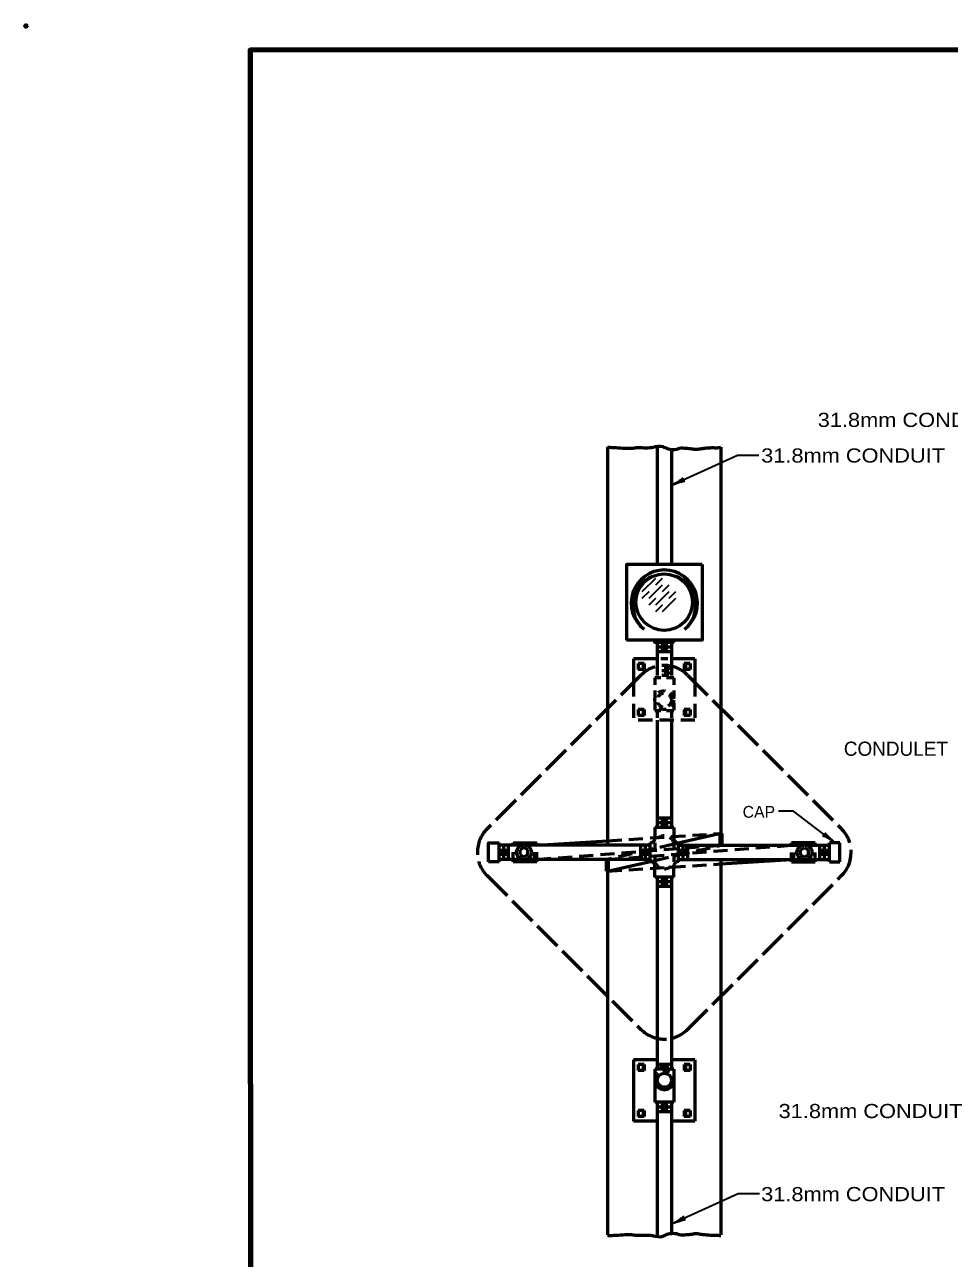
# Model space of a CAD drawing. Extents: x -31 to 825, y 0 to 544.
# Drawn here: x -31 to 204.1, y 230.5 to 544.3 of the extents above; entities that cross this region are included whole.
import ezdxf

# ---------------------------------------------------------------- set-up
doc = ezdxf.new("R2010")
doc.units = 0
doc.header["$LTSCALE"] = 1.2
doc.header["$PDMODE"] = 32
doc.header["$PDSIZE"] = 0.6
for name, pattern in [('LONG_DASHED', [7.5, 6, -1.5]), ('MEDIUM_DASHED', [4.5, 3, -1.5]), ('SHORT_DASHED', [2.7, 1.5, -1.2])]:
    doc.linetypes.add(name, pattern=pattern)
doc.layers.add('1', color=7, linetype='Continuous', lineweight=53)

msp = doc.modelspace()

# ---------------------------------------------------------------- linework, layer by layer
at = {"layer": '1'}
for p, q in [((117.259, 436.827), (117.259, 335.556)), ((129.859, 436.956), (129.859, 406.956)), ((133.459, 436.418), (133.459, 406.956)), ((146.059, 436.827), (146.059, 338.556)), ((129.859, 387.756), (129.859, 380.556)), ((132.559, 386.556), (130.759, 386.556)), ((133.459, 387.756), (133.459, 380.556)), ((134.059, 387.156), (134.059, 387.756)), ((129.859, 382.956), (123.859, 382.956)), ((123.859, 382.956), (123.859, 376.956)), ((133.459, 385.956), (129.859, 385.956)), ((133.459, 384.756), (129.859, 384.756)), ((132.559, 385.356), (130.759, 385.356)), ((132.559, 382.956), (130.759, 382.956)), ((139.459, 382.956), (133.459, 382.956)), ((139.459, 382.956), (139.459, 376.956)), ((125.059, 381.756), (125.059, 380.256)), ((126.559, 381.756), (125.059, 381.756)), ((126.559, 380.256), (125.059, 380.256)), ((126.259, 381.756), (126.259, 380.256)), ((126.559, 381.756), (126.559, 380.256)), ((136.759, 381.756), (136.759, 380.256)), ((138.259, 381.756), (136.759, 381.756)), ((138.259, 380.256), (136.759, 380.256)), ((137.059, 381.756), (137.059, 380.256)), ((138.259, 381.756), (138.259, 380.256)), ((129.859, 367.356), (129.859, 340.056)), ((133.459, 367.356), (133.459, 340.056)), ((133.459, 342.456), (129.859, 342.456)), ((134.059, 340.056), (129.259, 340.056)), ((129.259, 340.056), (129.259, 337.056)), ((133.459, 341.256), (129.859, 341.256)), ((132.559, 341.856), (130.759, 341.856)), ((132.559, 340.656), (130.759, 340.656)), ((134.059, 340.056), (134.059, 337.056)), ((89.659, 331.356), (89.659, 336.156)), ((93.259, 336.156), (99.259, 336.156)), ((93.259, 335.556), (93.259, 336.156)), ((99.259, 335.556), (117.259, 336.71)), ((128.059, 331.356), (128.059, 336.156)), ((146.059, 338.556), (134.059, 335.806)), ((135.259, 331.356), (135.259, 336.156)), ((170.037, 336.139), (164.037, 336.139)), ((164.037, 335.556), (164.037, 336.139)), ((170.037, 335.539), (170.037, 336.139)), ((173.638, 331.339), (173.638, 336.139)), ((176.338, 336.139), (173.638, 336.139)), ((176.338, 331.339), (176.338, 336.139)), ((95.336, 335.556), (89.659, 335.556)), ((90.259, 332.856), (90.259, 334.656)), ((90.859, 331.956), (90.859, 335.556)), ((91.459, 332.856), (91.459, 334.656)), ((92.059, 331.956), (92.059, 335.556)), ((95.982, 334.956), (94.98, 334.356)), ((94.98, 333.156), (94.98, 334.356)), ((94.98, 333.156), (95.982, 332.556)), ((96.984, 334.356), (95.982, 334.956)), ((96.984, 333.156), (95.982, 332.556)), ((96.984, 333.156), (96.984, 334.356)), ((125.659, 331.956), (125.659, 335.556)), ((126.259, 332.856), (126.259, 334.656)), ((126.859, 331.956), (126.859, 335.556)), ((127.459, 332.856), (127.459, 334.656)), ((135.859, 332.856), (135.859, 334.656)), ((136.459, 331.956), (136.459, 335.556)), ((137.059, 332.856), (137.059, 334.656)), ((137.659, 331.956), (137.659, 335.556)), ((166.312, 334.339), (167.314, 334.939)), ((166.312, 333.139), (166.312, 334.339)), ((166.312, 333.139), (167.314, 332.539)), ((167.314, 334.939), (168.316, 334.339)), ((168.316, 333.139), (167.314, 332.539)), ((167.911, 335.556), (173.659, 335.556)), ((168.316, 333.139), (168.316, 334.339)), ((171.238, 331.939), (171.238, 335.539)), ((171.838, 332.839), (171.838, 334.639)), ((172.438, 331.939), (172.438, 335.539)), ((173.037, 332.839), (173.037, 334.639)), ((89.659, 331.356), (86.959, 331.356)), ((95.383, 331.956), (89.659, 331.956)), ((93.259, 331.356), (93.259, 331.956)), ((99.259, 331.356), (93.259, 331.356)), ((99.259, 331.356), (99.259, 331.956)), ((117.259, 328.956), (129.259, 331.706)), ((129.259, 327.456), (129.259, 330.456)), ((134.059, 327.456), (134.059, 330.456)), ((146.059, 331.956), (146.059, 236.427)), ((146.059, 330.803), (164.037, 331.956)), ((164.037, 331.339), (164.037, 331.956)), ((164.037, 331.339), (170.037, 331.339)), ((167.963, 331.956), (173.659, 331.956)), ((170.037, 331.339), (170.037, 331.939)), ((173.638, 331.339), (176.338, 331.339)), ((117.259, 328.956), (117.259, 236.427)), ((134.059, 327.456), (129.259, 327.456)), ((129.859, 327.456), (129.859, 278.558)), ((132.559, 326.856), (130.759, 326.856)), ((133.459, 327.456), (133.459, 278.558)), ((133.459, 326.256), (129.859, 326.256)), ((133.459, 325.056), (129.859, 325.056)), ((132.559, 325.656), (130.759, 325.656)), ((123.859, 280.956), (123.859, 265.356)), ((129.859, 280.956), (123.859, 280.956)), ((125.059, 279.756), (125.059, 278.256)), ((126.559, 279.756), (125.059, 279.756)), ((126.259, 279.756), (126.259, 278.256)), ((126.559, 279.756), (126.559, 278.256)), ((133.459, 279.756), (129.859, 279.756)), ((139.459, 280.956), (133.459, 280.956)), ((136.759, 279.756), (136.759, 278.256)), ((138.259, 279.756), (136.759, 279.756)), ((137.059, 279.756), (137.059, 278.256)), ((138.259, 279.756), (138.259, 278.256)), ((139.459, 280.956), (139.459, 265.356)), ((126.559, 278.256), (125.059, 278.256)), ((134.059, 278.558), (129.259, 278.558)), ((129.259, 278.558), (129.259, 278.211)), ((129.259, 278.211), (129.259, 273.402)), ((132.859, 279.156), (130.459, 279.156)), ((134.059, 278.558), (134.059, 275.462)), ((138.259, 278.256), (136.759, 278.256)), ((129.259, 273.402), (129.259, 270.158)), ((134.059, 275.462), (134.059, 270.158)), ((134.059, 270.158), (129.259, 270.158)), ((129.859, 270.158), (129.859, 236.427)), ((133.459, 270.158), (133.459, 236.427)), ((125.059, 268.056), (125.059, 266.556)), ((126.559, 268.056), (125.059, 268.056)), ((126.259, 268.056), (126.259, 266.556)), ((126.559, 268.056), (126.559, 266.556)), ((133.459, 268.958), (129.859, 268.958)), ((133.459, 267.758), (129.859, 267.758)), ((129.859, 267.756), (129.859, 265.356)), ((132.559, 269.558), (130.759, 269.558)), ((132.559, 268.358), (130.759, 268.358)), ((133.459, 267.756), (133.459, 265.356)), ((136.759, 268.056), (136.759, 266.556)), ((138.259, 268.056), (136.759, 268.056)), ((137.059, 268.056), (137.059, 266.556)), ((138.259, 268.056), (138.259, 266.556)), ((129.859, 265.356), (123.859, 265.356)), ((126.559, 266.556), (125.059, 266.556)), ((139.459, 265.356), (133.459, 265.356)), ((138.259, 266.556), (136.759, 266.556))]:
    msp.add_line(p, q, dxfattribs=at)
at = {"layer": '1', "lineweight": 25}
for p, q in [((124.381, 400.118), (126.078, 401.815)), ((124.381, 400.118), (126.078, 401.815)), ((126.078, 398.421), (127.775, 400.118)), ((127.775, 396.724), (129.472, 398.421)), ((129.472, 395.027), (131.169, 396.724))]:
    msp.add_line(p, q, dxfattribs=at)
at = {"layer": '1', "lineweight": 35}
for p, q in [((126.078, 400.118), (129.472, 403.513)), ((127.775, 398.421), (131.169, 401.815)), ((129.472, 401.815), (131.169, 403.512)), ((131.169, 400.118), (132.866, 401.815)), ((126.078, 398.421), (127.775, 400.118)), ((129.472, 396.724), (132.866, 400.118)), ((132.866, 398.421), (134.563, 400.118)), ((127.775, 396.724), (129.472, 398.421)), ((129.472, 395.027), (131.169, 396.724)), ((131.169, 395.027), (134.563, 398.421))]:
    msp.add_line(p, q, dxfattribs=at)
at = {"layer": '1', "linetype": 'SHORT_DASHED'}
for p, q in [((133.459, 380.556), (129.859, 380.556)), ((129.859, 380.556), (129.859, 378.156)), ((132.859, 379.956), (130.459, 379.956)), ((133.459, 380.556), (133.459, 378.156)), ((134.059, 378.156), (129.259, 378.156)), ((129.259, 378.156), (129.259, 369.756)), ((133.459, 379.356), (129.859, 379.356)), ((132.859, 378.756), (130.459, 378.756)), ((134.059, 378.156), (134.059, 369.756)), ((125.059, 370.056), (125.059, 368.556)), ((126.559, 370.056), (125.059, 370.056)), ((126.559, 368.556), (125.059, 368.556)), ((126.259, 370.056), (126.259, 368.556)), ((126.559, 370.056), (126.559, 368.556)), ((134.059, 369.756), (129.259, 369.756)), ((129.859, 369.756), (129.859, 367.356)), ((133.459, 369.756), (133.459, 367.356)), ((136.759, 370.056), (136.759, 368.556)), ((138.259, 370.056), (136.759, 370.056)), ((138.259, 368.556), (136.759, 368.556)), ((137.059, 370.056), (137.059, 368.556)), ((138.259, 370.056), (138.259, 368.556)), ((129.259, 336.156), (129.259, 331.356)), ((134.059, 336.156), (134.059, 331.356)), ((93.259, 331.956), (93.259, 335.556)), ((98.659, 331.956), (98.659, 335.556)), ((99.259, 331.956), (99.259, 335.556)), ((164.037, 331.939), (164.037, 335.539)), ((164.638, 331.939), (164.638, 335.539)), ((170.037, 331.939), (170.037, 335.539))]:
    msp.add_line(p, q, dxfattribs=at)
at = {"layer": '1', "linetype": 'LONG_DASHED'}
for p, q in [((125.719, 378.817), (86.599, 339.696)), ((137.598, 378.817), (176.719, 339.696)), ((86.599, 327.817), (125.719, 288.696)), ((137.598, 288.696), (176.719, 327.817))]:
    msp.add_line(p, q, dxfattribs=at)
at = {"layer": '1', "linetype": 'MEDIUM_DASHED'}
for p, q in [((123.859, 376.956), (123.859, 367.356)), ((139.459, 376.956), (139.459, 367.356)), ((139.459, 367.356), (123.859, 367.356)), ((117.259, 336.71), (146.059, 338.556)), ((134.059, 335.806), (117.259, 331.956)), ((99.259, 331.956), (146.059, 335.556)), ((117.259, 331.956), (164.037, 335.556)), ((129.259, 331.706), (146.059, 335.556)), ((117.259, 328.956), (146.059, 330.803))]:
    msp.add_line(p, q, dxfattribs=at)
at = {"layer": '1', "lineweight": 90}
for p, q in [((146.059, 338.556), (146.059, 335.556)), ((117.259, 328.956), (117.259, 331.956))]:
    msp.add_line(p, q, dxfattribs=at)
at = {"layer": '1', "lineweight": 158}
msp.add_lwpolyline([(818.018, 537.903), (26.318, 537.803), (26.418, 11.803)], dxfattribs=at)
at = {"layer": '1', "lineweight": 35}
for points in [[(133.523, 427.157), (150.291, 434.803), (155.715, 434.803)], [(174.964, 336.277), (164.5, 344.223), (160.695, 344.223)], [(133.69, 239.294), (150.457, 246.94), (155.882, 246.94)]]:
    msp.add_lwpolyline(points, dxfattribs=at)
at = {"layer": '1'}
for points in [[(141.259, 406.956), (122.059, 406.956), (122.059, 387.756)], [(141.259, 406.956), (141.259, 387.756), (122.059, 387.756)], [(134.059, 387.156), (129.259, 387.156), (129.259, 387.756)], [(86.959, 331.356), (86.959, 336.156), (89.659, 336.156)], [(99.259, 335.556), (99.259, 335.572), (99.259, 336.156)], [(128.059, 335.556), (99.259, 335.556), (96.629, 335.556)], [(135.259, 335.556), (164.037, 335.556), (166.718, 335.556)], [(128.059, 331.956), (99.259, 331.956), (96.581, 331.956)], [(135.259, 331.956), (164.037, 331.956), (166.665, 331.956)]]:
    msp.add_lwpolyline(points, dxfattribs=at)
for centre, radius in [((131.645, 397.393), 7.2), ((95.982, 333.765), 1.905), ((167.314, 333.747), 1.905), ((131.678, 275.784), 1.8)]:
    msp.add_circle(centre, radius, dxfattribs=at)
at = {"layer": '1', "linetype": 'SHORT_DASHED'}
for centre, radius in [((131.653, 372.478), 2.4), ((131.678, 372.453), 1.8)]:
    msp.add_circle(centre, radius, dxfattribs=at)
at = {"layer": '1'}
for centre, radius, start, end in [((131.673, 397.168), 8.419, 307.40461, 232.59539), ((131.584, 396.593), 7.913, 111.48526, 230.57354), ((131.761, 396.593), 7.913, 309.42646, 68.51474), ((128.088, 337.367), 1.211, 268.60144, 345.13836), ((135.249, 337.367), 1.211, 194.86164, 271.39856), ((128.088, 330.168), 1.211, 14.86164, 91.39856), ((135.249, 330.168), 1.211, 88.60144, 165.13836), ((131.653, 275.809), 2.4, 183.91481, 351.69168)]:
    msp.add_arc(centre, radius, start, end, dxfattribs=at)
at = {"layer": '1', "linetype": 'LONG_DASHED'}
for centre, start, end in [((131.659, 372.877), 45, 135), ((92.538, 333.756), 135, 225.00094), ((170.779, 333.756), 315, 44.99965), ((131.659, 294.636), 224.99984, 315)]:
    msp.add_arc(centre, 8.4, start, end, dxfattribs=at)
at = {"layer": '1', "linetype": 'SHORT_DASHED'}
for centre, radius, start, end in [((131.659, 335.456), 2.5, 16.2602, 163.73979), ((131.659, 332.056), 2.5, 196.26021, 343.7398), ((131.653, 275.809), 2.4, 183.91481, 176.08519)]:
    msp.add_arc(centre, radius, start, end, dxfattribs=at)
at = {"layer": '1', "lineweight": 40}
for centre, major_axis, ratio, start_param, end_param in [((134.577, 428.002), (-1.872, -1.06), 0.122415, 0.8963533, 3.1415927), ((134.852, 427.484), (2.005, 0.683), 0.07063, 6.2823074, 8.5597026), ((173.721, 336.805), (1.82, -1.147), 0.122415, 0.8963533, 3.1415927), ((174.047, 337.292), (1.551, -1.443), 0.07063, 3.1407148, 5.41811), ((134.744, 240.139), (-1.872, -1.06), 0.122415, 0.8963533, 3.1415927), ((135.019, 239.621), (2.005, 0.683), 0.07063, 6.2823074, 8.5597026)]:
    msp.add_ellipse(centre, major_axis=major_axis, ratio=ratio, start_param=start_param, end_param=end_param, dxfattribs=at)
at = {"layer": '1'}
for points in [[(117.259, 436.827), (119.393, 436.705), (121.721, 436.568), (123.363, 436.568), (124.595, 436.705), (125.964, 436.705), (128.018, 436.705), (128.839, 436.842), (131.303, 436.979), (131.851, 436.705), (135.136, 436.431), (135.547, 436.568), (137.19, 436.568), (138.696, 436.431), (139.517, 436.294), (140.886, 436.431), (141.981, 436.568), (143.761, 436.705), (144.171, 436.705), (145.403, 436.705), (146.059, 436.827)], [(117.259, 236.237), (119.393, 236.358), (121.721, 236.495), (123.363, 236.495), (124.595, 236.358), (125.964, 236.358), (128.018, 236.358), (128.839, 236.221), (131.303, 236.085), (131.851, 236.358), (135.136, 236.632), (135.547, 236.495), (137.19, 236.495), (138.696, 236.632), (139.517, 236.769), (140.886, 236.632), (141.981, 236.495), (143.761, 236.358), (144.171, 236.358), (145.403, 236.358), (146.059, 236.237)]]:
    msp.add_spline(points, degree=3, dxfattribs=at)
msp.add_point((-30.682, 544.003), dxfattribs=at)

# ---------------------------------------------------------------- texts
at = {"layer": '1', "width": 1.15}
for p in [(170.679, 441.961), (156.297, 432.903), (160.736, 266.138), (156.297, 245.004)]:
    msp.add_text('31.8mm CONDUIT', height=3.6, dxfattribs=at).set_placement(p)
at = {"layer": '1'}
for s, height, p in [('CONDULET', 3.6, (177.315, 358.309)), ('CAP', 3, (151.589, 342.549))]:
    msp.add_text(s, height=height, dxfattribs=at).set_placement(p)

doc.saveas('drawing.dxf')
